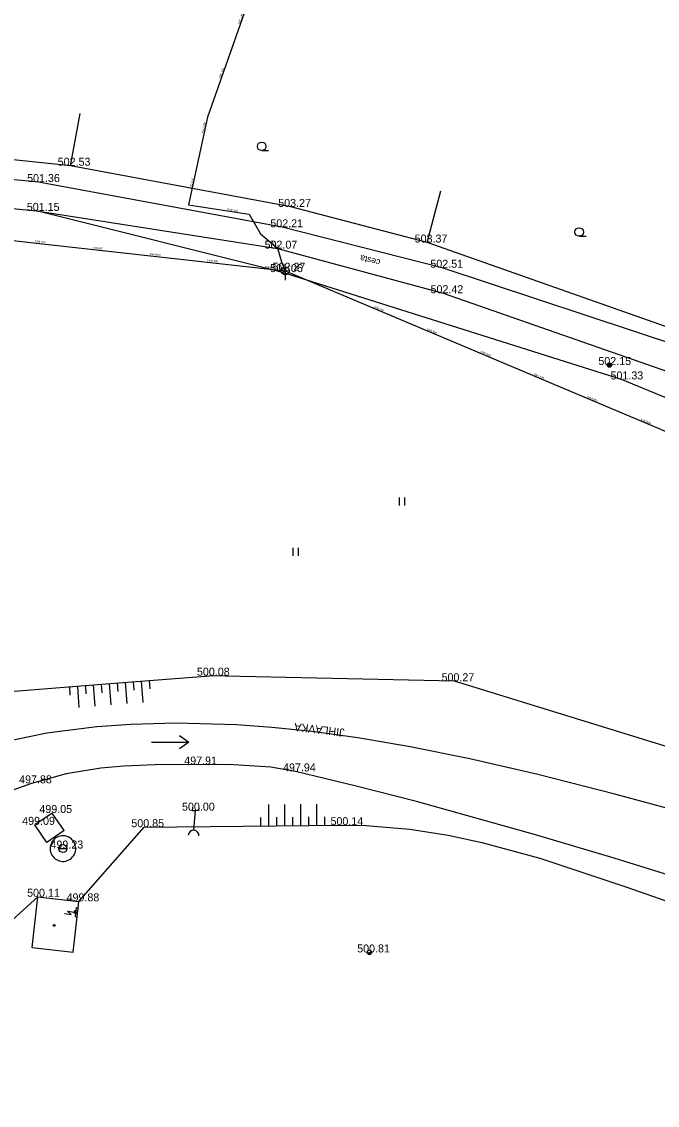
# Model space of a CAD drawing. Extents: x -668867 to -667827, y -1131943 to -1131019.
# Drawn here: x -668426.7 to -668367.1, y -1131620.9 to -1131519.3 of the extents above; entities that cross this region are included whole.
import ezdxf

# ---------------------------------------------------------------- set-up
doc = ezdxf.new("R2010")
doc.units = 0
for name, color, linetype in [('G_Bod_tecka', 7, 'Continuous'), ('G_Bod_vyska', 7, 'Continuous'), ('G_Breh_Teren', 7, 'Continuous'), ('G_Budovy-znacky', 7, 'Continuous'), ('G_Budovy_Objekty', 7, 'Continuous'), ('G_Cesty_Schody', 7, 'Continuous'), ('G_Objekty-Studny', 7, 'Continuous'), ('G_Ploty', 7, 'Continuous'), ('G_Popisy_Nazvy', 7, 'Continuous'), ('G_Popisy_povrchu', 7, 'Continuous'), ('G_Poznamky_odkaz', 7, 'Continuous'), ('G_Site-kanalizace', 7, 'Continuous'), ('G_Site-Rozvadece', 7, 'Continuous'), ('G_Site-Sloupy', 7, 'Continuous'), ('G_Vyskove_srafy', 7, 'Continuous'), ('G_Z_KANAL_podz_kotovane', 7, 'Continuous'), ('G_Zelen-Znacky', 7, 'Continuous'), ('Vrstva 12', 7, 'Continuous'), ('Vrstva 18', 7, 'Continuous'), ('Vrstva 2', 7, 'Continuous'), ('Vrstva 3', 7, 'Continuous'), ('Vrstva 8', 7, 'Continuous')]:
    doc.layers.add(name, color=color, linetype=linetype)

msp = doc.modelspace()

# ---------------------------------------------------------------- linework, layer by layer
at = {"layer": 'G_Bod_tecka'}
for p, q in [((-668422.1, -1131532.85), (-668422.1, -1131532.85)), ((-668425.1, -1131534.38), (-668425.1, -1131534.38)), ((-668401.44, -1131536.71), (-668401.44, -1131536.71)), ((-668425.29, -1131537.08), (-668425.29, -1131537.08)), ((-668402.24, -1131538.62), (-668402.24, -1131538.62)), ((-668402.69, -1131540.62), (-668402.69, -1131540.62)), ((-668388.65, -1131540.05), (-668388.65, -1131540.05)), ((-668402.3, -1131542.82), (-668402.3, -1131542.82)), ((-668401.96, -1131542.69), (-668401.96, -1131542.69)), ((-668387.24, -1131542.41), (-668387.24, -1131542.41)), ((-668387.15, -1131544.8), (-668387.15, -1131544.8)), ((-668371.57, -1131551.53), (-668371.57, -1131551.53)), ((-668370.43, -1131552.88), (-668370.43, -1131552.88)), ((-668409.02, -1131580.65), (-668409.02, -1131580.65)), ((-668386.11, -1131581.17), (-668386.11, -1131581.17)), ((-668410.32, -1131588.98), (-668410.32, -1131588.98)), ((-668401, -1131589.62), (-668401, -1131589.62)), ((-668425.74, -1131590.74), (-668425.74, -1131590.74)), ((-668423.82, -1131593.52), (-668423.82, -1131593.52)), ((-668410.39, -1131593.3), (-668410.39, -1131593.3)), ((-668425.44, -1131594.63), (-668425.44, -1131594.63)), ((-668396.65, -1131594.66), (-668396.65, -1131594.66)), ((-668415.19, -1131594.85), (-668415.19, -1131594.85)), ((-668422.8, -1131596.85), (-668422.8, -1131596.85)), ((-668425.16, -1131601.37), (-668425.16, -1131601.37)), ((-668421.3, -1131601.8), (-668421.3, -1131601.8)), ((-668394.07, -1131606.59), (-668394.07, -1131606.59))]:
    msp.add_line(p, q, dxfattribs=at)
at = {"layer": 'G_Breh_Teren'}
for points in [[(-668402.3, -1131542.82), (-668425.29, -1131537.08)], [(-668370.43, -1131552.88), (-668402.3, -1131542.82)], [(-668349.97, -1131561.31), (-668370.43, -1131552.88)], [(-668479.79, -1131610.64), (-668473.05, -1131605.83), (-668466.31, -1131601.03), (-668458.5, -1131595.46), (-668450.66, -1131589.91), (-668448.19, -1131588.31), (-668445.93, -1131587.06), (-668443.88, -1131586.07), (-668440.18, -1131584.6), (-668437.32, -1131583.72), (-668435.14, -1131583.17), (-668431.84, -1131582.56), (-668428.54, -1131582.18), (-668418.78, -1131581.41), (-668409.02, -1131580.65)], [(-668386.11, -1131581.17), (-668409.02, -1131580.65)], [(-668360.48, -1131589.08), (-668386.11, -1131581.17)], [(-668362.99, -1131593.93), (-668371.08, -1131591.74), (-668378.28, -1131589.91), (-668384.65, -1131588.44), (-668390.25, -1131587.31), (-668395.16, -1131586.48), (-668399.46, -1131585.89), (-668403.21, -1131585.5), (-668406.49, -1131585.26), (-668412.2, -1131585.09), (-668416.45, -1131585.21), (-668419.61, -1131585.44), (-668424.32, -1131586.05), (-668428.97, -1131586.99)], [(-668361.28, -1131600.81), (-668371.12, -1131597.75), (-668378.5, -1131595.55), (-668389.65, -1131592.44), (-668395.3, -1131590.99), (-668401, -1131589.62), (-668403.32, -1131589.22), (-668406.82, -1131589.01), (-668410.32, -1131588.98), (-668414.19, -1131589), (-668417.08, -1131589.13), (-668419.25, -1131589.33), (-668422.5, -1131589.86), (-668425.74, -1131590.74), (-668428.03, -1131591.58)], [(-668415.19, -1131594.85), (-668405.92, -1131594.75), (-668396.65, -1131594.66), (-668394.42, -1131594.69), (-668390.28, -1131595.04), (-668386.68, -1131595.6), (-668383.55, -1131596.28), (-668378.11, -1131597.76), (-668370.03, -1131600.44), (-668362.02, -1131603.26), (-668343.64, -1131609.6), (-668334.51, -1131612.86), (-668325.43, -1131616.28), (-668314.41, -1131620.56), (-668303.4, -1131624.83)], [(-668421.3, -1131601.8), (-668415.19, -1131594.85)], [(-668425.16, -1131601.37), (-668436.76, -1131611.89)]]:
    msp.add_lwpolyline(points, dxfattribs=at)
at = {"layer": 'G_Budovy-znacky'}
msp.add_circle((-668423.61, -1131604.05), 0.0875, dxfattribs=at)
at = {"layer": 'G_Budovy_Objekty'}
for p, q in [((-668425.69, -1131606.14), (-668425.16, -1131601.37)), ((-668425.16, -1131601.37), (-668421.3, -1131601.8)), ((-668421.37, -1131602.44), (-668421.3, -1131601.8)), ((-668421.46, -1131603.24), (-668421.37, -1131602.44)), ((-668421.83, -1131606.57), (-668421.46, -1131603.24)), ((-668425.69, -1131606.14), (-668421.83, -1131606.57))]:
    msp.add_line(p, q, dxfattribs=at)
at = {"layer": 'G_Cesty_Schody'}
for p, q in [((-668357.3, -1131552.36), (-668387.24, -1131542.41)), ((-668387.15, -1131544.8), (-668351.44, -1131557.29)), ((-668423.82, -1131593.52), (-668425.44, -1131594.63)), ((-668422.69, -1131595.17), (-668423.82, -1131593.52)), ((-668424.3, -1131596.28), (-668425.44, -1131594.63)), ((-668422.69, -1131595.17), (-668424.3, -1131596.28))]:
    msp.add_line(p, q, dxfattribs=at)
for points in [[(-668425.1, -1131534.38), (-668457.23, -1131531.26)], [(-668456.04, -1131534.08), (-668425.29, -1131537.08)], [(-668402.24, -1131538.62), (-668425.1, -1131534.38)], [(-668425.29, -1131537.08), (-668402.69, -1131540.62)], [(-668387.24, -1131542.41), (-668402.24, -1131538.62)], [(-668402.69, -1131540.62), (-668387.15, -1131544.8)], [(-668421.6, -1131596.85), (-668421.61, -1131596.7), (-668421.64, -1131596.55), (-668421.68, -1131596.41), (-668421.75, -1131596.27), (-668421.83, -1131596.14), (-668421.93, -1131596.03), (-668422.04, -1131595.92), (-668422.16, -1131595.84), (-668422.3, -1131595.76), (-668422.44, -1131595.71), (-668422.59, -1131595.67), (-668422.74, -1131595.66), (-668422.89, -1131595.66), (-668423.04, -1131595.68), (-668423.18, -1131595.72), (-668423.33, -1131595.78), (-668423.46, -1131595.85), (-668423.58, -1131595.94), (-668423.69, -1131596.05), (-668423.78, -1131596.16), (-668423.86, -1131596.3), (-668423.92, -1131596.43), (-668423.97, -1131596.58), (-668423.99, -1131596.73), (-668424, -1131596.88), (-668423.99, -1131597.03), (-668423.96, -1131597.18), (-668423.9, -1131597.32), (-668423.84, -1131597.46), (-668423.75, -1131597.58), (-668423.65, -1131597.7), (-668423.54, -1131597.8), (-668423.41, -1131597.88), (-668423.28, -1131597.95), (-668423.14, -1131598.01), (-668422.99, -1131598.04), (-668422.84, -1131598.05), (-668422.69, -1131598.05), (-668422.54, -1131598.02), (-668422.39, -1131597.98), (-668422.25, -1131597.92), (-668422.12, -1131597.84), (-668422, -1131597.75), (-668421.9, -1131597.64), (-668421.8, -1131597.52), (-668421.73, -1131597.39), (-668421.67, -1131597.25), (-668421.63, -1131597.1), (-668421.6, -1131596.96), (-668421.6, -1131596.85)]]:
    msp.add_lwpolyline(points, dxfattribs=at)
at = {"layer": 'G_Objekty-Studny'}
msp.add_lwpolyline([(-668423.18, -1131596.85), (-668422.43, -1131596.85)], dxfattribs=at)
msp.add_circle((-668422.8, -1131596.85), 0.375, dxfattribs=at)
at = {"layer": 'G_Ploty'}
for p, q in [((-668422.1, -1131532.85), (-668421.19, -1131527.94)), ((-668422.1, -1131532.85), (-668456.6, -1131529.31)), ((-668401.44, -1131536.71), (-668422.1, -1131532.85)), ((-668388.65, -1131540.05), (-668387.38, -1131535.21)), ((-668388.65, -1131540.05), (-668401.44, -1131536.71)), ((-668365.27, -1131548.3), (-668388.65, -1131540.05))]:
    msp.add_line(p, q, dxfattribs=at)
at = {"layer": 'G_Popisy_Nazvy'}
for p, q in [((-668411.87, -1131586.27), (-668411, -1131586.89)), ((-668414.5, -1131586.89), (-668411, -1131586.89)), ((-668411, -1131586.89), (-668411.87, -1131587.51))]:
    msp.add_line(p, q, dxfattribs=at)
at = {"layer": 'G_Site-kanalizace'}
for p, q in [((-668401.96, -1131542.31), (-668401.96, -1131543.56)), ((-668410.67, -1131592.98), (-668410.69, -1131593.28)), ((-668410.69, -1131593.28), (-668410.39, -1131593.3)), ((-668410.52, -1131595.13), (-668410.39, -1131593.3)), ((-668410.09, -1131593.32), (-668410.39, -1131593.3)), ((-668410.07, -1131593.02), (-668410.09, -1131593.32))]:
    msp.add_line(p, q, dxfattribs=at)
msp.add_circle((-668401.96, -1131542.69), 0.375, dxfattribs=at)
msp.add_arc((-668410.55, -1131595.63), 0.5, 356.0554, 176.0554, dxfattribs=at)
at = {"layer": 'G_Site-Rozvadece'}
for p, q in [((-668422.04, -1131603.02), (-668422.38, -1131602.73)), ((-668422.38, -1131602.73), (-668421.51, -1131602.83)), ((-668421.77, -1131602.91), (-668421.51, -1131602.83)), ((-668421.51, -1131602.83), (-668421.74, -1131602.69)), ((-668421.57, -1131602.42), (-668421.66, -1131603.22)), ((-668421.37, -1131602.44), (-668421.57, -1131602.42)), ((-668422.66, -1131602.95), (-668422.04, -1131603.02)), ((-668421.66, -1131603.22), (-668421.46, -1131603.24))]:
    msp.add_line(p, q, dxfattribs=at)
at = {"layer": 'G_Site-Sloupy'}
for centre, radius in [((-668371.57, -1131551.53), 0.2), ((-668371.57, -1131551.53), 0.16), ((-668371.57, -1131551.53), 0.12), ((-668371.57, -1131551.53), 0.08), ((-668371.57, -1131551.53), 0.04), ((-668394.07, -1131606.59), 0.2)]:
    msp.add_circle(centre, radius, dxfattribs=at)
for radius in [0.18, 0.16, 0.14, 0.12, 0.1, 0.08, 0.06, 0.04, 0.02]:
    msp.add_arc((-668394.07, -1131606.59), radius, 180, 0, dxfattribs=at)
at = {"layer": 'G_Vyskove_srafy'}
for points in [[(-668419.21, -1131581.45), (-668419.15, -1131582.24)], [(-668418.46, -1131581.39), (-668418.3, -1131583.38)], [(-668417.71, -1131581.33), (-668417.65, -1131582.13)], [(-668416.96, -1131581.27), (-668416.81, -1131583.27)], [(-668416.22, -1131581.21), (-668416.16, -1131582.01)], [(-668415.47, -1131581.16), (-668415.31, -1131583.15)], [(-668414.72, -1131581.1), (-668414.66, -1131581.89)], [(-668422.2, -1131581.68), (-668422.14, -1131582.48)], [(-668421.45, -1131581.62), (-668421.3, -1131583.62)], [(-668420.7, -1131581.56), (-668420.64, -1131582.36)], [(-668419.96, -1131581.51), (-668419.8, -1131583.5)], [(-668403.49, -1131594.73), (-668403.51, -1131592.73)], [(-668401.99, -1131594.71), (-668402.01, -1131592.71)], [(-668400.49, -1131594.7), (-668400.51, -1131592.7)], [(-668398.99, -1131594.68), (-668399.01, -1131592.68)], [(-668404.24, -1131594.74), (-668404.25, -1131593.94)], [(-668402.74, -1131594.72), (-668402.75, -1131593.92)], [(-668401.24, -1131594.7), (-668401.25, -1131593.9)], [(-668399.74, -1131594.69), (-668399.75, -1131593.89)], [(-668398.24, -1131594.67), (-668398.25, -1131593.87)]]:
    msp.add_lwpolyline(points, dxfattribs=at)
at = {"layer": 'G_Z_KANAL_podz_kotovane'}
for p, q in [((-668409.26, -1131528.31), (-668411.04, -1131536.52)), ((-668401.96, -1131542.69), (-668352.5, -1131563.6))]:
    msp.add_line(p, q, dxfattribs=at)
for points in [[(-668403.07, -1131511.65), (-668405.81, -1131518.54), (-668409.26, -1131528.31)], [(-668411.04, -1131536.52), (-668405.33, -1131537.39), (-668404.28, -1131539.22), (-668402.69, -1131540.56), (-668402.31, -1131541.87), (-668401.96, -1131542.69)], [(-668435.53, -1131538.95), (-668433.14, -1131539.22), (-668401.96, -1131542.69)]]:
    msp.add_lwpolyline(points, dxfattribs=at)
at = {"layer": 'G_Zelen-Znacky'}
for p, q in [((-668404.17, -1131531.43), (-668403.52, -1131531.43)), ((-668374.41, -1131539.46), (-668373.76, -1131539.46)), ((-668391.26, -1131564.69), (-668391.26, -1131563.94)), ((-668390.76, -1131564.69), (-668390.76, -1131563.94)), ((-668401.22, -1131569.4), (-668401.22, -1131568.65)), ((-668400.72, -1131569.4), (-668400.72, -1131568.65))]:
    msp.add_line(p, q, dxfattribs=at)
for centre in [(-668404.17, -1131531.03), (-668374.41, -1131539.06)]:
    msp.add_circle(centre, 0.403, dxfattribs=at)
at = {"layer": 'Vrstva 12'}
for p, q in [((-668409.26, -1131528.31), (-668411.04, -1131536.52)), ((-668401.96, -1131542.69), (-668352.5, -1131563.6))]:
    msp.add_line(p, q, dxfattribs=at)
for points in [[(-668411.04, -1131536.52), (-668405.33, -1131537.39), (-668404.28, -1131539.22), (-668402.69, -1131540.56), (-668402.31, -1131541.87), (-668401.96, -1131542.69)], [(-668435.53, -1131538.95), (-668433.14, -1131539.22), (-668401.96, -1131542.69)]]:
    msp.add_lwpolyline(points, dxfattribs=at)
at = {"layer": 'Vrstva 18'}
msp.add_lwpolyline([(-668403.07, -1131511.65), (-668405.81, -1131518.54), (-668409.26, -1131528.31)], dxfattribs=at)
at = {"layer": 'Vrstva 8'}
msp.add_line((-668401.96, -1131542.69), (-668401.96, -1131542.69), dxfattribs=at)

# ---------------------------------------------------------------- texts
at = {"layer": 'G_Bod_vyska'}
for s, p in [('502.53', (-668423.29, -1131532.85)), ('501.36', (-668426.16, -1131534.38)), ('501.15', (-668426.19, -1131537.08)), ('503.27', (-668402.62, -1131536.71)), ('502.21', (-668403.36, -1131538.62)), ('503.37', (-668389.83, -1131540.05)), ('502.07', (-668403.9, -1131540.62)), ('502.51', (-668388.36, -1131542.41)), ('501.06', (-668403.38, -1131542.82)), ('502.27', (-668403.15, -1131542.69)), ('502.42', (-668388.34, -1131544.8)), ('502.15', (-668372.61, -1131551.53)), ('501.33', (-668371.47, -1131552.88)), ('500.08', (-668410.24, -1131580.65)), ('500.27', (-668387.31, -1131581.17)), ('497.91', (-668411.43, -1131588.98)), ('497.94', (-668402.17, -1131589.62)), ('497.88', (-668426.91, -1131590.74)), ('500.00', (-668411.64, -1131593.3)), ('499.05', (-668425.01, -1131593.52)), ('499.09', (-668426.62, -1131594.63)), ('500.85', (-668416.39, -1131594.85)), ('500.14', (-668397.72, -1131594.66)), ('499.23', (-668423.97, -1131596.85)), ('500.11', (-668426.16, -1131601.37)), ('499.88', (-668422.46, -1131601.8)), ('500.81', (-668395.22, -1131606.59))]:
    msp.add_text(s, height=0.75, dxfattribs=at).set_placement(p)
at = {"layer": 'G_Popisy_povrchu'}
msp.add_text('cesta', height=0.6, rotation=165.8129, dxfattribs=at).set_placement((-668393.01, -1131541.67))
at = {"layer": 'G_Poznamky_odkaz'}
msp.add_text('JIHLAVKA', height=0.75, rotation=173.174, dxfattribs=at).set_placement((-668396.37, -1131585.63))
at = {"layer": 'Vrstva 2'}
msp.add_text('502.27 (498.62)', height=0.1316, dxfattribs=at).set_placement((-668401.75, -1131542.34))
at = {"layer": 'Vrstva 3'}
for s, rotation, p in [('PVC 150', 70.5807, (-668406.23, -1131519.58)), ('PVC 150', 70.56, (-668408.02, -1131524.65)), ('PVC 150', 77.7771, (-668409.63, -1131529.78)), ('PVC 150', 77.7699, (-668410.77, -1131535.03)), ('PVC 150', 351.3482, (-668407.39, -1131537.02)), ('KAM 600', 353.6332, (-668425.46, -1131540)), ('PVC 150', 319.8765, (-668403.35, -1131539.94)), ('KAM 600', 353.6651, (-668420.06, -1131540.6)), ('KAM 600', 353.642, (-668414.66, -1131541.2)), ('KAM 600', 353.6492, (-668409.26, -1131541.8)), ('KAM 600', 353.6616, (-668403.86, -1131542.41)), ('KAM 600', 337.0907, (-668393.69, -1131546.11)), ('KAM 600', 337.0782, (-668388.69, -1131548.23)), ('KAM 600', 337.0907, (-668383.68, -1131550.34)), ('KAM 600', 337.0782, (-668378.67, -1131552.46)), ('KAM 600', 337.0782, (-668373.67, -1131554.57)), ('KAM 600', 337.0782, (-668368.66, -1131556.69))]:
    msp.add_text(s, height=0.176, rotation=rotation, dxfattribs=at).set_placement(p)

doc.saveas('drawing.dxf')
